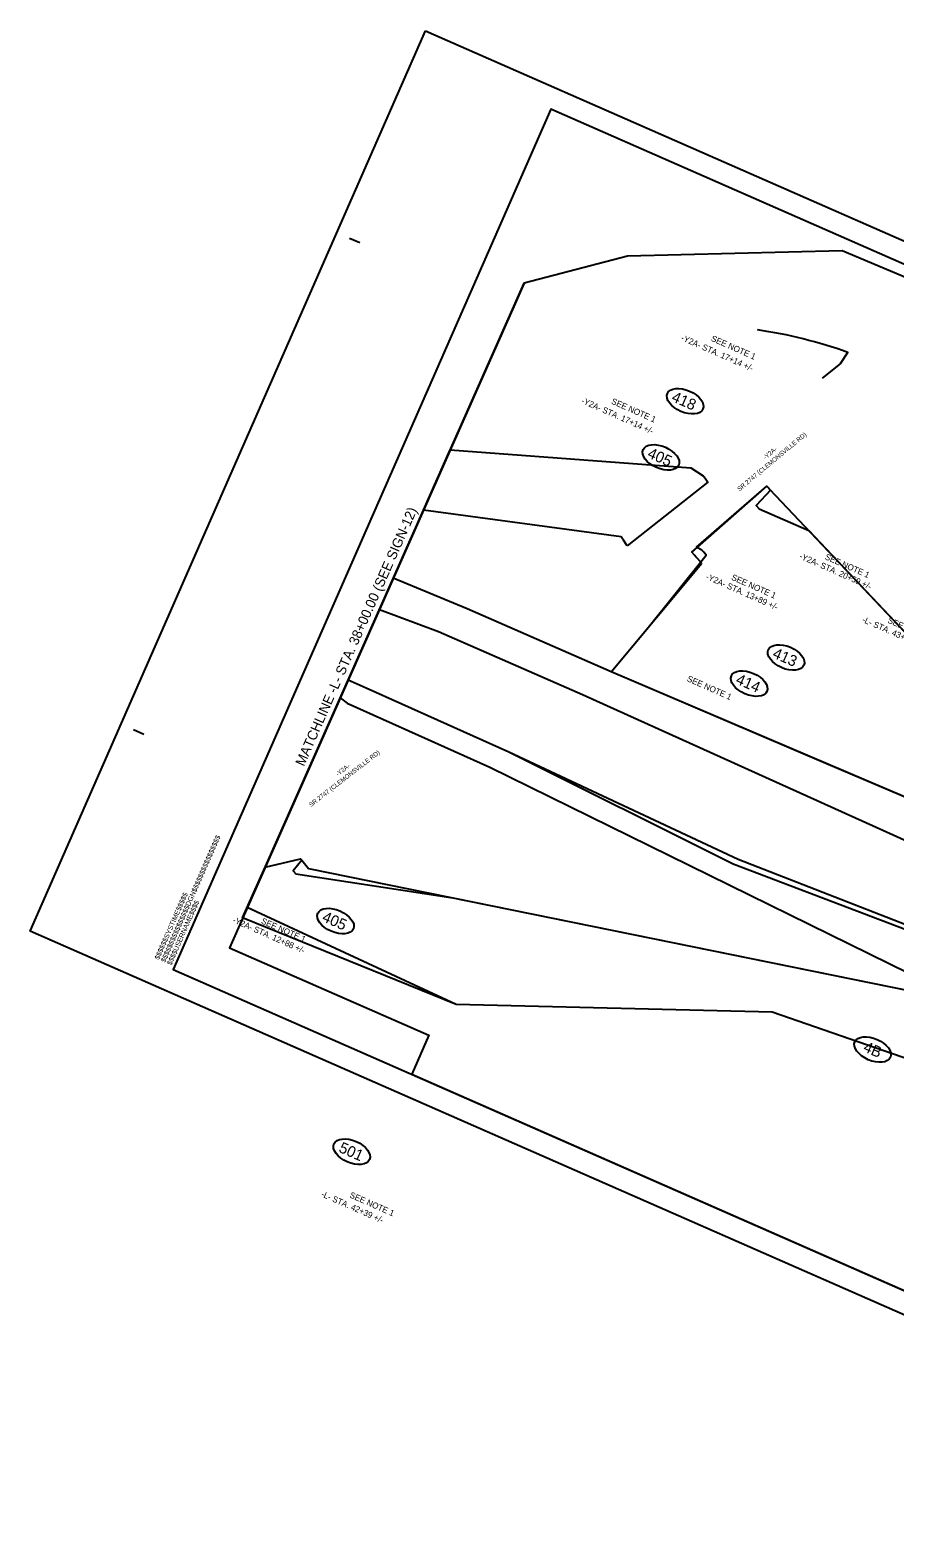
# Model space of a CAD drawing. Extents: x 1639021 to 1641149, y 842052 to 843739.
# Drawn here: x 1639021 to 1639988, y 842052 to 843739 of the extents above; entities that cross this region are included whole.
import ezdxf

# ---------------------------------------------------------------- set-up
doc = ezdxf.new("R2010")
doc.units = 0
for name, color, linetype in [('Default', 7, 'Continuous'), ('Exist Mkg Solid Double Yellow', 7, 'Continuous'), ('Exist Mkg Solid White Stop Bar', 7, 'Continuous'), ('Prop Easement Permanent Drainage Utility', 7, 'Continuous'), ('Prop Horizontal Alignment', 7, 'Continuous'), ('Prop Horizontal Alignment Tick Small', 7, 'Continuous'), ('Prop ROW Marker CA CELL', 7, 'Continuous'), ('Prop ROW Marker CELL', 7, 'Continuous'), ('Prop ROW Text', 7, 'Continuous'), ('Prop Sign E Speed Limit XX CELL', 7, 'Continuous'), ('Scratch_Level_2', 7, 'Continuous')]:
    doc.layers.add(name, color=color, linetype=linetype)

msp = doc.modelspace()

# ---------------------------------------------------------------- linework, layer by layer
at = {"layer": 'Exist Mkg Solid Double Yellow'}
msp.add_arc((1639754.6, 842866.1), 543.7, 70.5168, 81.5265, dxfattribs=at)
at = {"layer": 'Exist Mkg Solid White Stop Bar'}
msp.add_lwpolyline([(1639935.9, 843378.7), (1639927.3, 843365.9), (1639907.1, 843349.8)], dxfattribs=at)
at = {"layer": 'Prop Horizontal Alignment Tick Small'}
msp.add_lwpolyline([(1640037.7, 843446.6), (1639929.5, 843492.2), (1639689.3, 843486.4), (1639573.7, 843456), (1639244.3, 842712.5), (1639467.3, 842614.6), (1639448.2, 842571.1), (1640243.3, 842221.8)], dxfattribs=at)
for points in [[(1639689, 843162.3), (1639684.9, 843168.6), (1639683.7, 843170.2), (1639682.3, 843172.1), (1639461, 843202), (1639491.1, 843269.7), (1639760.2, 843249.4), (1639774, 843240.5), (1639774.9, 843239.6), (1639776.1, 843238), (1639779.4, 843233.5)], [(1639772.5, 843143), (1639766, 843149.8), (1639764.6, 843151.3), (1639761.4, 843155.1), (1639845.3, 843228.9), (1639847.3, 843226.8), (1639848.6, 843225.3), (1639854.9, 843218.5), (1640103.6, 842955.8), (1640292.2, 842856.4), (1640629.1, 842742.4), (1640617.7, 842617.6), (1639671.2, 843021.3)], [(1639411.8, 843090.8), (1639477.8, 843066.5), (1639639, 842996), (1640597.3, 842562.8), (1640617.7, 842617.6), (1639671.2, 843021.3), (1639510, 843091.7), (1639427.4, 843126.2)], [(1640549.9, 842462.9), (1640578.7, 842512.8), (1639807.4, 842806), (1639556.5, 842931.2), (1639397, 843003), (1639376.8, 843012), (1639368, 842992.1), (1639375.7, 842986.3), (1639535.2, 842914.5), (1640071.7, 842651)], [(1640549.9, 842462.9), (1640578.7, 842512.8), (1639813.1, 842811.3), (1639556.5, 842931.2), (1639397, 843003), (1639376.8, 843012), (1639368, 842992.1), (1639375.7, 842986.3), (1639535.2, 842914.5), (1640071.7, 842651)], [(1640509.9, 842393.5), (1640258.3, 842499.5), (1639851.3, 842640.6), (1639497.7, 842649), (1639258.8, 842746), (1639284.1, 842802.8), (1639323.7, 842812.1), (1639324.9, 842810.5), (1639332.6, 842801.1), (1640071.7, 842651), (1640549.9, 842462.9)]]:
    msp.add_lwpolyline(points, close=True, dxfattribs=at)
at = {"layer": 'Prop ROW Marker CA CELL'}
msp.add_line((1639263.8, 842757.1), (1639573.7, 843456), dxfattribs=at)
at = {"layer": 'Prop ROW Marker CELL'}
for p, q in [((1639464.7, 843739.1), (1639464.7, 843739.1)), ((1639463.1, 843716.8), (1639463.1, 843716.8)), ((1639604.8, 843650.3), (1639604.8, 843650.3)), ((1639378.4, 843506.5), (1639389.8, 843501.4)), ((1639136.8, 842956.6), (1639148.2, 842951.5)), ((1639181.1, 842688.4), (1639181.1, 842688.4)), ((1639181.1, 842688.4), (1639181.1, 842688.4)), ((1639181.1, 842688.4), (1639181.1, 842688.4)), ((1639181.1, 842688.4), (1639181.1, 842688.4)), ((1639181.1, 842688.4), (1639181.1, 842688.4)), ((1639181.1, 842688.4), (1639181.1, 842688.4)), ((1639181.1, 842688.4), (1639181.1, 842688.4)), ((1639181.1, 842688.4), (1639181.1, 842688.4))]:
    msp.add_line(p, q, dxfattribs=at)
msp.add_lwpolyline([(1640976.5, 843047.7), (1639603.8, 843650.7), (1639181.1, 842688.4), (1640553.8, 842085.4)], close=True, dxfattribs=at)
at = {"layer": 'Prop ROW Text'}
msp.add_lwpolyline([(1639463.6, 843738.4), (1641009, 843059.5), (1640566.6, 842052.4), (1639021.2, 842731.3)], close=True, dxfattribs=at)
at = {"layer": 'Prop Sign E Speed Limit XX CELL'}
for centre in [(1639753.9, 843324), (1639726.8, 843261.1), (1639866.8, 843037.3), (1639825.5, 843008.1), (1639362.8, 842742.4), (1639963.6, 842598.7), (1639380.9, 842484.4)]:
    msp.add_ellipse(centre, major_axis=(-19.9, 8.7), ratio=0.571429, dxfattribs=at)
at = {"layer": 'Scratch_Level_2'}
msp.add_line((1639284.1, 842802.8), (1639284.1, 842802.8), dxfattribs=at)
msp.add_lwpolyline([(1639845.3, 843228.9), (1639849.4, 843224.5), (1639833.3, 843207.2), (1639836.6, 843203.6), (1639892.1, 843179.2), (1640103.6, 842955.8), (1640292.2, 842856.4), (1640629.1, 842742.4), (1640617.7, 842617.6), (1640595.7, 842627), (1640408.6, 842706.8), (1640278.3, 842762.4), (1640109.7, 842834.3), (1639911.3, 842918.8), (1639760.4, 842983.2), (1639671.2, 843021.3), (1639711, 843069.1), (1639777.2, 843151.7), (1639774.6, 843155.2), (1639772.5, 843157.2), (1639766.7, 843160.6)], close=True, dxfattribs=at)
msp.add_lwpolyline([(1639284.1, 842802.8), (1639323.7, 842812.1), (1639324.9, 842810.5), (1639315.5, 842798.5), (1639318.2, 842795.3), (1639494, 842768.3), (1639987.2, 842668.2), (1640071.7, 842651), (1640171.9, 842611.6), (1640533.9, 842469.2), (1640549.9, 842462.9), (1640509.9, 842393.5), (1640280.7, 842490), (1640234.7, 842507.7), (1639851.3, 842640.6), (1639497.7, 842649), (1639264, 842757.5), (1639284.1, 842802.8)], dxfattribs=at)

# ---------------------------------------------------------------- texts
at = {"layer": 'Default'}
for s, height, p in [('-Y2A- STA. 17+14 +/-', 6.771, (1639748.6, 843392.5)), ('SEE NOTE 1', 6.77, (1639782.2, 843391.8)), ('-Y2A- STA. 17+14 +/-', 6.771, (1639637, 843322.2)), ('SEE NOTE 1', 6.77, (1639670.6, 843321.5)), ('-Y2A- STA. 20+59 +/-', 6.771, (1639880.9, 843148.3)), ('SEE NOTE 1', 6.77, (1639909.6, 843147.5)), ('-Y2A- STA. 13+89 +/-', 6.771, (1639776.4, 843125.3)), ('SEE NOTE 1', 6.77, (1639805, 843124.5)), ('-L- STA. 43+63 +/-', 6.771, (1639951.2, 843077.3)), ('SEE NOTE 1', 6.77, (1639979.8, 843076.5)), ('SEE NOTE 1', 6.77, (1639755.3, 843011.1)), ('-Y2A- STA. 12+88 +/-', 6.771, (1639247, 842741.2)), ('SEE NOTE 1', 6.77, (1639278.9, 842740.1)), ('-L- STA. 42+39 +/-', 6.771, (1639346, 842434.6)), ('SEE NOTE 1', 6.77, (1639377.9, 842433.5))]:
    msp.add_text(s, height=height, rotation=336.1242, dxfattribs=at).set_placement(p)
at = {"layer": 'Prop Easement Permanent Drainage Utility'}
msp.add_text('MATCHLINE -L- STA. 38+00.00 (SEE SIGN-12)', height=11, rotation=66.173, dxfattribs=at).set_placement((1639327.4, 842914.8))
at = {"layer": 'Prop Horizontal Alignment'}
for s, rotation, p in [('SR 2747 (CLEMONSVILLE RD)', 39.7691, (1639814.7, 843223)), ('-Y2A-', 39.7691, (1639843.6, 843258.4)), ('SR 2747 (CLEMONSVILLE RD)', 37.8269, (1639335.4, 842869.8)), ('-Y2A-', 37.8269, (1639365.4, 842904.2))]:
    msp.add_text(s, height=5, rotation=rotation, dxfattribs=at).set_placement(p)
at = {"layer": 'Prop ROW Marker CELL'}
for s, p in [('$$$$$$$$$$$$$$$$DGN$$$$$$$$$$$$$$$$', (1639172.2, 842695.7)), ('$$$$$$SYSTIME$$$$$', (1639165.2, 842698.7)), ('$$$$USERNAME$$$$', (1639179.1, 842692.6))]:
    msp.add_text(s, height=5.581, rotation=66.285, dxfattribs=at).set_placement(p)
at = {"layer": 'Prop Sign E Speed Limit XX CELL'}
for s, p in [('418', (1639737.7, 843324.4)), ('405', (1639710.7, 843261.4)), ('413', (1639850.7, 843037.6)), ('414', (1639809.5, 843008.5)), ('405', (1639346.8, 842742.7)), ('4B', (1639952.2, 842597.1)), ('501', (1639365.5, 842484.5))]:
    msp.add_text(s, height=12.27, rotation=336.285, dxfattribs=at).set_placement(p)

doc.saveas('drawing.dxf')
